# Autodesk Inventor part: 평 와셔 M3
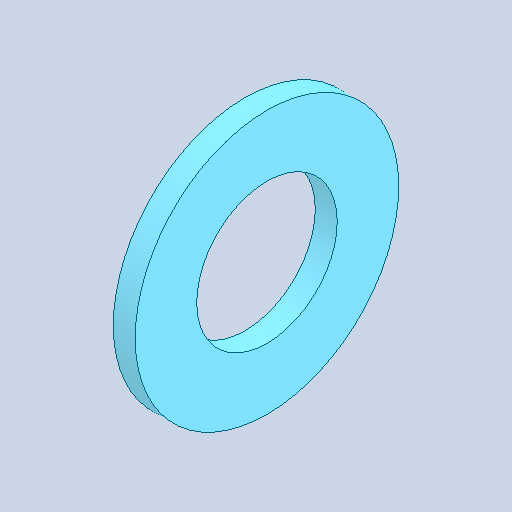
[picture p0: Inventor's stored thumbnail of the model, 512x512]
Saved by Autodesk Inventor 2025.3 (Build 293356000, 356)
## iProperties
Created: 2025-09
Part Number: 평 와셔 M3
Material: 강철, 연강
Description: 평면 와셔
Document SubType Name: Modeling
Designer: PC-15
Density: 7.85 g/cm^3
Appearance: 기본값
Author: jhkim
Sending System: Autodesk Inventor 2026
Preprocessor: ST-DEVELOPER v20.1
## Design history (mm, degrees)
feature "Solid1"
node "솔리드1"
